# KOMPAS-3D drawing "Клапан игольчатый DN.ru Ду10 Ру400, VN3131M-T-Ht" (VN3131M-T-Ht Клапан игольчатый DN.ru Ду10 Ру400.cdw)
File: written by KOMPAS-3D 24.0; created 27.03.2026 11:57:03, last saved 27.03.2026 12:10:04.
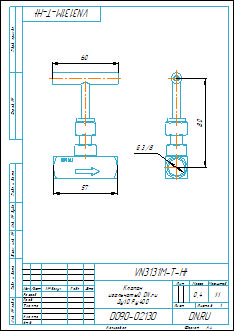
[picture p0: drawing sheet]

Document properties: Автор: Илья; Форматы листов документа: A4; Полное имя файла: VN3131M-T-Ht Клапан игольчатый DN.ru Ду10 Ру400.m3d; Масса: 0.4; Наименование: Клапан игольчатый DN.ru Ду10 Ру400; Количество листов документа: 1; Примечание: D090-02130

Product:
- Body: Body3  | qty 1
    Масса: 0.224966
- Part/product: Клапан игольчатый DN.ru Ду10 Ру400  | designation VN3131M-T-Ht
    Масса: 0.4
    Раздел спецификации: Прочие изделия
    Примечание: D090-02130

Views: Вид 1, Слева, Проекционный вид 2
Referenced files in D:\Обмен\Заказы с фриланса\DN.ru\VNxxM-T-Ht Клапан игольчатый DN.ru Ду8-50 Ру400\VN3232M-T-Ht Клапан игольчатый DN.ru Ду8-50 Ру400\DN8\: VN3232M-T-Ht Клапан игольчатый DN.ru Ду8 Ру400.m3d, VN3232M-T-Ht Клапан игольчатый DN.ru Ду8 Ру400.cdw
Referenced files in D:\Обмен\Заказы с фриланса\DN.ru\VNxxM-T-Ht Клапан игольчатый DN.ru Ду8-50 Ру400\VN3131M-T-Ht Клапан игольчатый DN.ru Ду8-50 Ру400\DN10\: VN3131M-T-Ht Клапан игольчатый DN.ru Ду10 Ру400.m3d
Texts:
  VN3131M-T-Ht
  Клапан
  игольчатый DN.ru
  Ду10 Ру400
  Body3
  Клапан игольчатый DN.ru Ду10 Ру400
  VN3131M-T-Ht Клапан игольчатый DN.ru Ду10 Ру400
Dimensions and other numbers on the sheet: 0; 3; 2; 4; 57; 60; 80; 1:1; 1; 0,4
